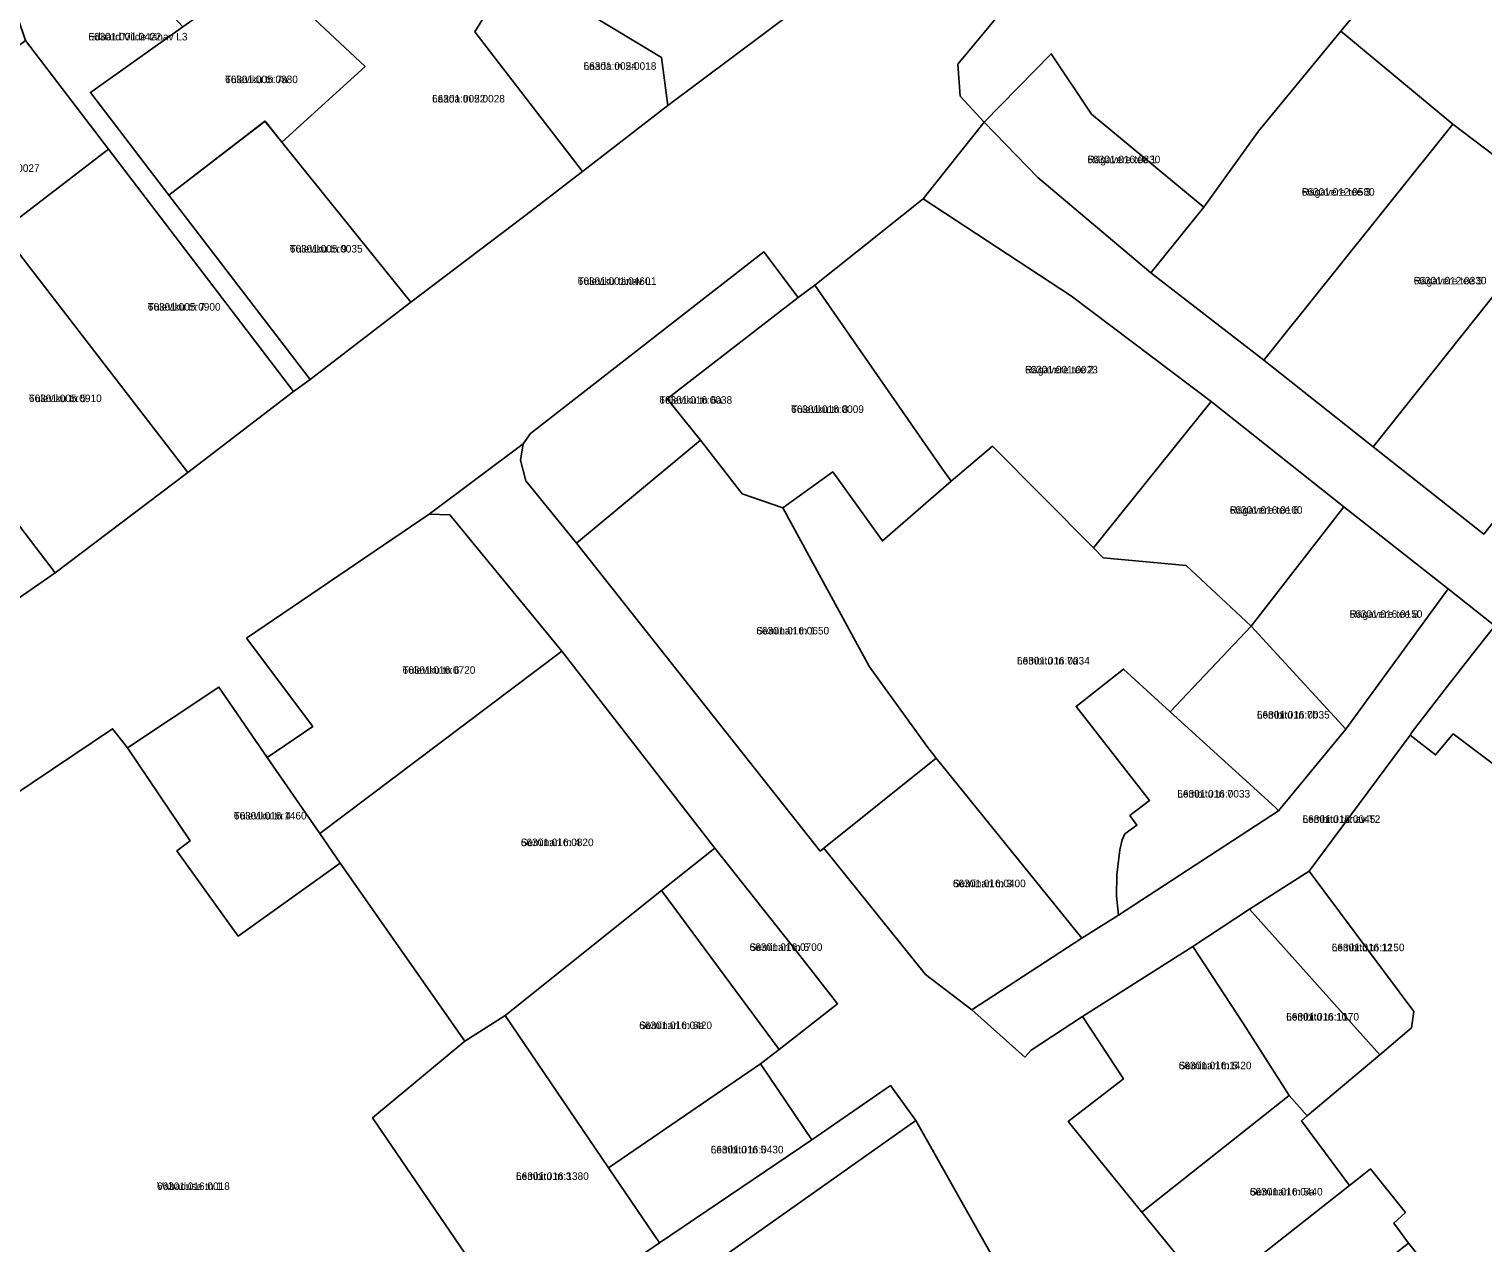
# Model space of a CAD drawing. Extents: x 632278 to 636344, y 6578401 to 6583362.
# Drawn here: x 634548.1 to 634837.7, y 6580768.1 to 6581009.9 of the extents above; entities that cross this region are included whole.
import ezdxf

# ---------------------------------------------------------------- set-up
doc = ezdxf.new("R2010")
doc.units = 0
for name, color, linetype in [('L_AADRESS', 7, 'Continuous'), ('PIIR', 7, 'Continuous'), ('TUNNUS', 7, 'Continuous')]:
    doc.layers.add(name, color=color, linetype=linetype)

msp = doc.modelspace()

# ---------------------------------------------------------------- linework, layer by layer
at = {"layer": 'PIIR'}
for points in [[(634522.63, 6581181.47), (634558.5, 6581126.08), (634562.6, 6581124.73), (634572.96, 6581115.49), (634571.9, 6581106.52), (634574.81, 6581101.96), (634577.54, 6581100.62), (634578, 6581099.98), (634578.36, 6581096.81), (634588.53, 6581083.81), (634601.18, 6581071.74), (634611.53, 6581064.36), (634617.41, 6581060.76), (634675.34, 6581025.98), (634694.43, 6581038.46), (634707.46, 6581018.72), (634675.35, 6580994.7), (634674.12, 6581004.24), (634644.69, 6581022.07), (634617.7, 6581038.36), (634616.67, 6581039.01), (634588.9, 6581055.77), (634554, 6581089.57), (634541.61, 6581098.39)], [(634790.34, 6581071.74), (634733.15, 6581002.97), (634733.61, 6580996.53), (634738.4, 6580991.36), (634726.23, 6580976.08), (634704.63, 6580958.94), (634701.34, 6580956.42), (634694.52, 6580965.53), (634648.02, 6580929.38), (634646.55, 6580927.27), (634627.84, 6580913.27), (634591.45, 6580888.58), (634604.69, 6580871), (634595.56, 6580864.8), (634585.94, 6580878.83), (634567.73, 6580866.74), (634564.77, 6580870.55), (634500.9, 6580827.64)], [(634517.89, 6580877.02), (634553.36, 6580901.62), (634579.74, 6580921.58), (634600.83, 6580937.71), (634604.11, 6580940.13), (634624.15, 6580955.5), (634646.91, 6580972.75), (634658.35, 6580981.56), (634675.35, 6580994.7), (634707.46, 6581018.72)], [(634840.08, 6580891.01), (634830.79, 6580898.44), (634810.03, 6580914.75), (634783.62, 6580935.76), (634755.77, 6580956.73), (634726.23, 6580976.08), (634738.4, 6580991.36), (634749.09, 6580980.36), (634771.58, 6580961.38), (634794.1, 6580943.95), (634815.84, 6580926.73), (634837.9, 6580909.32)], [(634740.71, 6580764.18), (634724.78, 6580792.46), (634719.75, 6580799.45), (634704.04, 6580788.61), (634693.8, 6580803.76), (634697.55, 6580806.61), (634709.19, 6580815.75), (634701.19, 6580825.95), (634684.73, 6580846.73), (634654.28, 6580886.01), (634631.96, 6580913.12), (634627.84, 6580913.27), (634646.55, 6580927.27), (634646.02, 6580924.03), (634647.1, 6580919.9), (634657.18, 6580907.54), (634705.74, 6580846.17), (634706.47, 6580846.76), (634726.7, 6580821.57), (634735.93, 6580814.56), (634746.49, 6580805.11), (634747.76, 6580806.49), (634758, 6580813.21), (634766.11, 6580800.76), (634755.12, 6580792.29), (634769.78, 6580774.21), (634783.36, 6580757.62)]]:
    msp.add_lwpolyline(points, dxfattribs=at)
for points in [[(634759.79, 6580993), (634751.74, 6581005.03), (634738.4, 6580991.36), (634733.61, 6580996.53), (634733.15, 6581002.97), (634790.34, 6581071.74), (634797.56, 6581064.7), (634816.61, 6581047.12), (634823.5, 6581036.63), (634816.8, 6581018.45), (634809.41, 6581009.48), (634793, 6580989.57), (634782.13, 6580974.46)], [(634515.79, 6581057.74), (634522.08, 6581062.96), (634526.35, 6581057.91), (634558.01, 6581021.92), (634563.03, 6581027.57), (634578.76, 6581010.38), (634560.35, 6580997.32), (634575.99, 6580976.83), (634604.11, 6580940.13), (634600.83, 6580937.71), (634563.93, 6580986.03), (634547.42, 6581007.65), (634538.39, 6581034.25)], [(634831.74, 6580991), (634809.41, 6581009.48), (634816.8, 6581018.45), (634823.5, 6581036.63), (634838.59, 6581047), (634847.95, 6581056.76), (634903.28, 6581012.64), (634850.41, 6580976.85)], [(634616.67, 6581039.01), (634617.7, 6581038.36), (634644.69, 6581022.07), (634636.92, 6581009.38), (634658.35, 6580981.56), (634646.91, 6580972.75), (634624.15, 6580955.5), (634598.46, 6580987.41), (634615.08, 6581002.5), (634602, 6581014.69), (634609.54, 6581027.18)], [(634644.69, 6581022.07), (634674.12, 6581004.24), (634675.35, 6580994.7), (634658.35, 6580981.56), (634636.92, 6581009.38)], [(634560.35, 6580997.32), (634578.76, 6581010.38), (634594.49, 6581021.49), (634601.09, 6581015.56), (634602, 6581014.69), (634615.08, 6581002.5), (634598.46, 6580987.41), (634595.11, 6580991.55), (634575.99, 6580976.83)], [(634507.4, 6580976.97), (634516.04, 6580983.42), (634547.42, 6581007.65), (634563.93, 6580986.03), (634542.73, 6580969.7), (634524.03, 6580955.3), (634513.33, 6580969.26)], [(634771.58, 6580961.38), (634782.13, 6580974.46), (634793, 6580989.57), (634809.41, 6581009.48), (634831.74, 6580991), (634794.1, 6580943.95)], [(634759.79, 6580993), (634782.13, 6580974.46), (634771.58, 6580961.38), (634749.09, 6580980.36), (634738.4, 6580991.36), (634751.74, 6581005.03)], [(634575.99, 6580976.83), (634595.14, 6580991.57), (634598.46, 6580987.41), (634624.15, 6580955.5), (634604.11, 6580940.13)], [(634831.74, 6580991), (634850.41, 6580976.85), (634853.77, 6580974.29), (634815.84, 6580926.73), (634794.1, 6580943.95)], [(634563.93, 6580986.03), (634600.83, 6580937.71), (634579.74, 6580921.58), (634542.73, 6580969.7)], [(634704.63, 6580958.94), (634726.23, 6580976.08), (634755.77, 6580956.73), (634783.62, 6580935.76), (634760.19, 6580906.59), (634740.02, 6580926.83), (634731.8, 6580919.85), (634729.96, 6580922.44)], [(634815.84, 6580926.73), (634853.77, 6580974.29), (634875.44, 6580957), (634862.3, 6580940.1), (634850.08, 6580924.68), (634837.9, 6580909.32)], [(634516.45, 6580949.48), (634524.03, 6580955.3), (634542.73, 6580969.7), (634579.74, 6580921.58), (634553.36, 6580901.62), (634531.7, 6580929.87)], [(634648.02, 6580929.38), (634694.52, 6580965.53), (634701.34, 6580956.42), (634675.27, 6580936.27), (634681.89, 6580928.06), (634657.18, 6580907.54), (634647.1, 6580919.9), (634646.02, 6580924.03), (634646.55, 6580927.27)], [(634704.63, 6580958.94), (634729.96, 6580922.44), (634731.8, 6580919.85), (634718.12, 6580907.96), (634708.21, 6580921.69), (634698.26, 6580914.54), (634690.18, 6580917.34), (634681.89, 6580928.06), (634675.27, 6580936.27), (634701.34, 6580956.42)], [(634810.03, 6580914.75), (634791.58, 6580890.98), (634778.62, 6580903.06), (634762.1, 6580904.61), (634760.19, 6580906.59), (634783.62, 6580935.76)], [(634495.16, 6580905.04), (634531.7, 6580929.87), (634553.36, 6580901.62), (634517.89, 6580877.02)], [(634681.89, 6580928.06), (634690.18, 6580917.34), (634698.26, 6580914.54), (634715.53, 6580882.9), (634727.16, 6580866.79), (634728.81, 6580864.67), (634706.47, 6580846.76), (634705.74, 6580846.17), (634657.18, 6580907.54)], [(634698.26, 6580914.54), (634708.21, 6580921.69), (634718.12, 6580907.96), (634731.8, 6580919.85), (634740.02, 6580926.83), (634760.19, 6580906.59), (634762.1, 6580904.61), (634778.62, 6580903.06), (634791.58, 6580890.98), (634775.46, 6580873.9), (634766.16, 6580882.43), (634756.7, 6580874.97), (634771.35, 6580856.25), (634767.42, 6580853.23), (634768.77, 6580851.31), (634766.42, 6580849.58), (634765.85, 6580848.37), (634765.38, 6580846.39), (634764.8, 6580841.43), (634764.73, 6580837.21), (634765.17, 6580833.42), (634757.86, 6580828.79), (634728.81, 6580864.67), (634727.16, 6580866.79), (634715.53, 6580882.9)], [(634606.02, 6580849.68), (634595.56, 6580864.8), (634604.69, 6580871), (634591.45, 6580888.58), (634627.84, 6580913.27), (634631.96, 6580913.12), (634654.28, 6580886.01)], [(634810.03, 6580914.75), (634830.79, 6580898.44), (634810.45, 6580870.42), (634791.58, 6580890.98)], [(634735.93, 6580814.56), (634757.86, 6580828.79), (634765.17, 6580833.42), (634797.02, 6580854.15), (634810.45, 6580870.42), (634830.79, 6580898.44), (634840.08, 6580891.01), (634835.86, 6580885.68), (634830.65, 6580878.99), (634823.64, 6580869.94), (634823.24, 6580869.23), (634803.09, 6580842.19), (634791.25, 6580834.56), (634779.94, 6580827.16), (634758, 6580813.21), (634747.76, 6580806.49), (634746.49, 6580805.11)], [(634775.46, 6580873.9), (634791.58, 6580890.98), (634810.45, 6580870.42), (634797.02, 6580854.15), (634796.42, 6580854.85)], [(634840.08, 6580891.01), (634861.06, 6580874.76), (634847.15, 6580857.94), (634831.8, 6580869.51), (634828.29, 6580865.31), (634823.24, 6580869.23), (634823.64, 6580869.94), (634830.65, 6580878.99), (634835.86, 6580885.68)], [(634634.91, 6580808.28), (634610.11, 6580843.74), (634606.02, 6580849.68), (634654.28, 6580886.01), (634684.73, 6580846.73), (634674.14, 6580838.33), (634642.97, 6580813.42)], [(634756.7, 6580874.97), (634766.16, 6580882.43), (634775.46, 6580873.9), (634796.42, 6580854.85), (634797.02, 6580854.15), (634765.17, 6580833.42), (634764.73, 6580837.21), (634764.8, 6580841.43), (634765.38, 6580846.39), (634765.85, 6580848.37), (634766.42, 6580849.58), (634768.77, 6580851.31), (634767.42, 6580853.23), (634771.35, 6580856.25)], [(634577.58, 6580846.19), (634580.2, 6580848.23), (634567.73, 6580866.74), (634585.94, 6580878.83), (634595.56, 6580864.8), (634606.02, 6580849.68), (634610.11, 6580843.74), (634589.79, 6580829.23)], [(634567.73, 6580866.74), (634580.2, 6580848.23), (634577.58, 6580846.19), (634589.79, 6580829.23), (634610.11, 6580843.74), (634634.91, 6580808.28), (634616.55, 6580793.04), (634646.33, 6580749.29), (634566.55, 6580694.43), (634562.08, 6580690.88), (634551.68, 6580703.87), (634546.86, 6580710.5), (634528.99, 6580734.85), (634502.24, 6580770.97), (634501.39, 6580811.99), (634500.9, 6580827.64), (634564.77, 6580870.55)], [(634823.24, 6580869.23), (634828.29, 6580865.31), (634831.8, 6580869.51), (634847.15, 6580857.94), (634862.57, 6580846.46), (634870.06, 6580838.92), (634888.87, 6580818.57), (634892.77, 6580814.98), (634907.16, 6580795.65), (634873.8, 6580767.13), (634843.07, 6580742.91), (634840.06, 6580746.68), (634822.92, 6580768.08), (634819.98, 6580772.06), (634822.28, 6580774.15), (634815.33, 6580782.85), (634813.98, 6580781.78), (634811.16, 6580779.56), (634801.59, 6580792.39), (634802.72, 6580793.42), (634817.17, 6580805.59), (634823.5, 6580810.97), (634823.96, 6580814.19), (634803.09, 6580842.19)], [(634757.86, 6580828.79), (634735.93, 6580814.56), (634726.7, 6580821.57), (634706.47, 6580846.76), (634728.81, 6580864.67)], [(634684.73, 6580846.73), (634701.19, 6580825.95), (634709.19, 6580815.75), (634697.55, 6580806.61), (634674.14, 6580838.33)], [(634823.96, 6580814.19), (634823.5, 6580810.97), (634817.17, 6580805.59), (634791.25, 6580834.56), (634803.09, 6580842.19)], [(634697.55, 6580806.61), (634693.8, 6580803.76), (634663.54, 6580783.07), (634642.97, 6580813.42), (634674.14, 6580838.33)], [(634799.14, 6580797.48), (634790.04, 6580811.74), (634779.94, 6580827.16), (634791.25, 6580834.56), (634817.17, 6580805.59), (634802.72, 6580793.42)], [(634755.12, 6580792.29), (634766.11, 6580800.76), (634758, 6580813.21), (634779.94, 6580827.16), (634790.04, 6580811.74), (634799.14, 6580797.48), (634769.78, 6580774.21)], [(634616.55, 6580793.04), (634634.91, 6580808.28), (634642.97, 6580813.42), (634663.54, 6580783.07), (634673.7, 6580768.11), (634646.33, 6580749.29)], [(634663.54, 6580783.07), (634693.8, 6580803.76), (634704.04, 6580788.61), (634673.7, 6580768.11)], [(634704.04, 6580788.61), (634719.75, 6580799.45), (634724.78, 6580792.46), (634651.97, 6580741), (634630.12, 6580723.26), (634568.5, 6580680.22), (634562.08, 6580690.88), (634566.55, 6580694.43), (634646.33, 6580749.29), (634673.7, 6580768.11)], [(634802.72, 6580793.42), (634801.59, 6580792.39), (634811.16, 6580779.56), (634783.36, 6580757.62), (634769.78, 6580774.21), (634799.14, 6580797.48)], [(634724.78, 6580792.46), (634740.71, 6580764.18), (634710.44, 6580741.96), (634671.82, 6580713.32), (634651.97, 6580741)], [(634815.33, 6580782.85), (634822.28, 6580774.15), (634819.98, 6580772.06), (634822.92, 6580768.08), (634793.5, 6580744.88), (634783.36, 6580757.62), (634811.15, 6580779.53), (634813.98, 6580781.78)]]:
    msp.add_lwpolyline(points, close=True, dxfattribs=at)

# ---------------------------------------------------------------- texts
at = {"layer": 'L_AADRESS'}
for s, p in [('Eduard Vilde tänav L3', (634559.95, 6581007.67)), ('Laada tn 24', (634658.59, 6581001.82)), ('Tuleviku tn 7a', (634587.17, 6580999.16)), ('Laada tn 22', (634628.41, 6580995.31)), ('Rägavere tee 1', (634758.96, 6580983.21)), ('Rägavere tee 3', (634801.66, 6580976.74)), ('Tuleviku tn 9', (634600.07, 6580965.41)), ('Tuleviku tänav L1', (634657.41, 6580958.97)), ('Rägavere tee 5', (634823.94, 6580959.06)), ('Tuleviku tn 7', (634571.78, 6580953.84)), ('Rägavere tee 2', (634746.53, 6580941.33)), ('Tuleviku tn 5', (634548.1, 6580935.61)), ('Tuleviku tn 6a', (634673.68, 6580935.29)), ('Tuleviku tn 8', (634699.93, 6580933.45)), ('Rägavere tee 6', (634787.3, 6580913.37)), ('Rägavere tee 8', (634811.18, 6580892.64)), ('Seminari tn 1', (634693, 6580889.32)), ('Tuleviku tn 6', (634622.53, 6580881.48)), ('Lembitu tn 7a', (634744.92, 6580883.34)), ('Lembitu tn 7b', (634792.71, 6580872.57)), ('Lembitu tn 7', (634776.86, 6580856.83)), ('Tuleviku tn 4', (634588.92, 6580852.46)), ('Lembitu tänav T2', (634801.8, 6580851.78)), ('Seminari tn 4', (634646.09, 6580847.15)), ('Seminari tn 3', (634732.16, 6580838.97)), ('Seminari tn 6', (634691.66, 6580826.28)), ('Lembitu tn 12', (634807.61, 6580826.21)), ('Lembitu tn 10', (634798.55, 6580812.4)), ('Seminari tn 6a', (634669.67, 6580810.7)), ('Seminari tn 5', (634777.13, 6580802.7)), ('Lembitu tn 5', (634683.91, 6580785.94)), ('Lembitu tn 3', (634645.12, 6580780.65)), ('Vabaduse tn 1', (634573.61, 6580778.65)), ('Seminari tn 5a', (634791.3, 6580777.55))]:
    msp.add_text(s, height=1.5, dxfattribs=at).set_placement(p)
at = {"layer": 'TUNNUS'}
for s, p in [('66301:001:0422', (634559.95, 6581007.67)), ('66301:005:0018', (634658.59, 6581001.82)), ('66301:005:0880', (634587.17, 6580999.16)), ('66301:005:0028', (634628.41, 6580995.31)), ('66301:016:0830', (634758.96, 6580983.21)), ('66301:005:0027', (634535.73, 6580981.48)), ('66301:012:0580', (634801.66, 6580976.74)), ('66301:005:0035', (634600.07, 6580965.41)), ('66301:001:0460', (634657.41, 6580958.97)), ('66301:012:0330', (634823.94, 6580959.06)), ('66301:005:0900', (634571.78, 6580953.84)), ('66301:001:0023', (634746.53, 6580941.33)), ('66301:005:0910', (634548.1, 6580935.61)), ('66301:016:0038', (634673.68, 6580935.29)), ('66301:016:0009', (634699.93, 6580933.45)), ('66301:016:0100', (634787.3, 6580913.37)), ('66301:016:0150', (634811.18, 6580892.64)), ('66301:016:0650', (634693, 6580889.32)), ('66301:016:0720', (634622.53, 6580881.48)), ('66301:016:0034', (634744.92, 6580883.34)), ('66301:016:0035', (634792.71, 6580872.57)), ('66301:016:0033', (634776.86, 6580856.83)), ('66301:016:1460', (634588.92, 6580852.46)), ('66301:016:0045', (634801.8, 6580851.78)), ('66301:016:0820', (634646.09, 6580847.15)), ('66301:016:0400', (634732.16, 6580838.97)), ('66301:016:0700', (634691.66, 6580826.28)), ('66301:016:1150', (634807.61, 6580826.21)), ('66301:016:1170', (634798.55, 6580812.4)), ('66301:016:0420', (634669.67, 6580810.7)), ('66301:016:1420', (634777.13, 6580802.7)), ('66301:016:0430', (634683.91, 6580785.94)), ('66301:016:1380', (634645.12, 6580780.65)), ('66301:016:0018', (634573.61, 6580778.65)), ('66301:016:0440', (634791.3, 6580777.55))]:
    msp.add_text(s, height=1.5, dxfattribs=at).set_placement(p)

doc.saveas('drawing.dxf')
